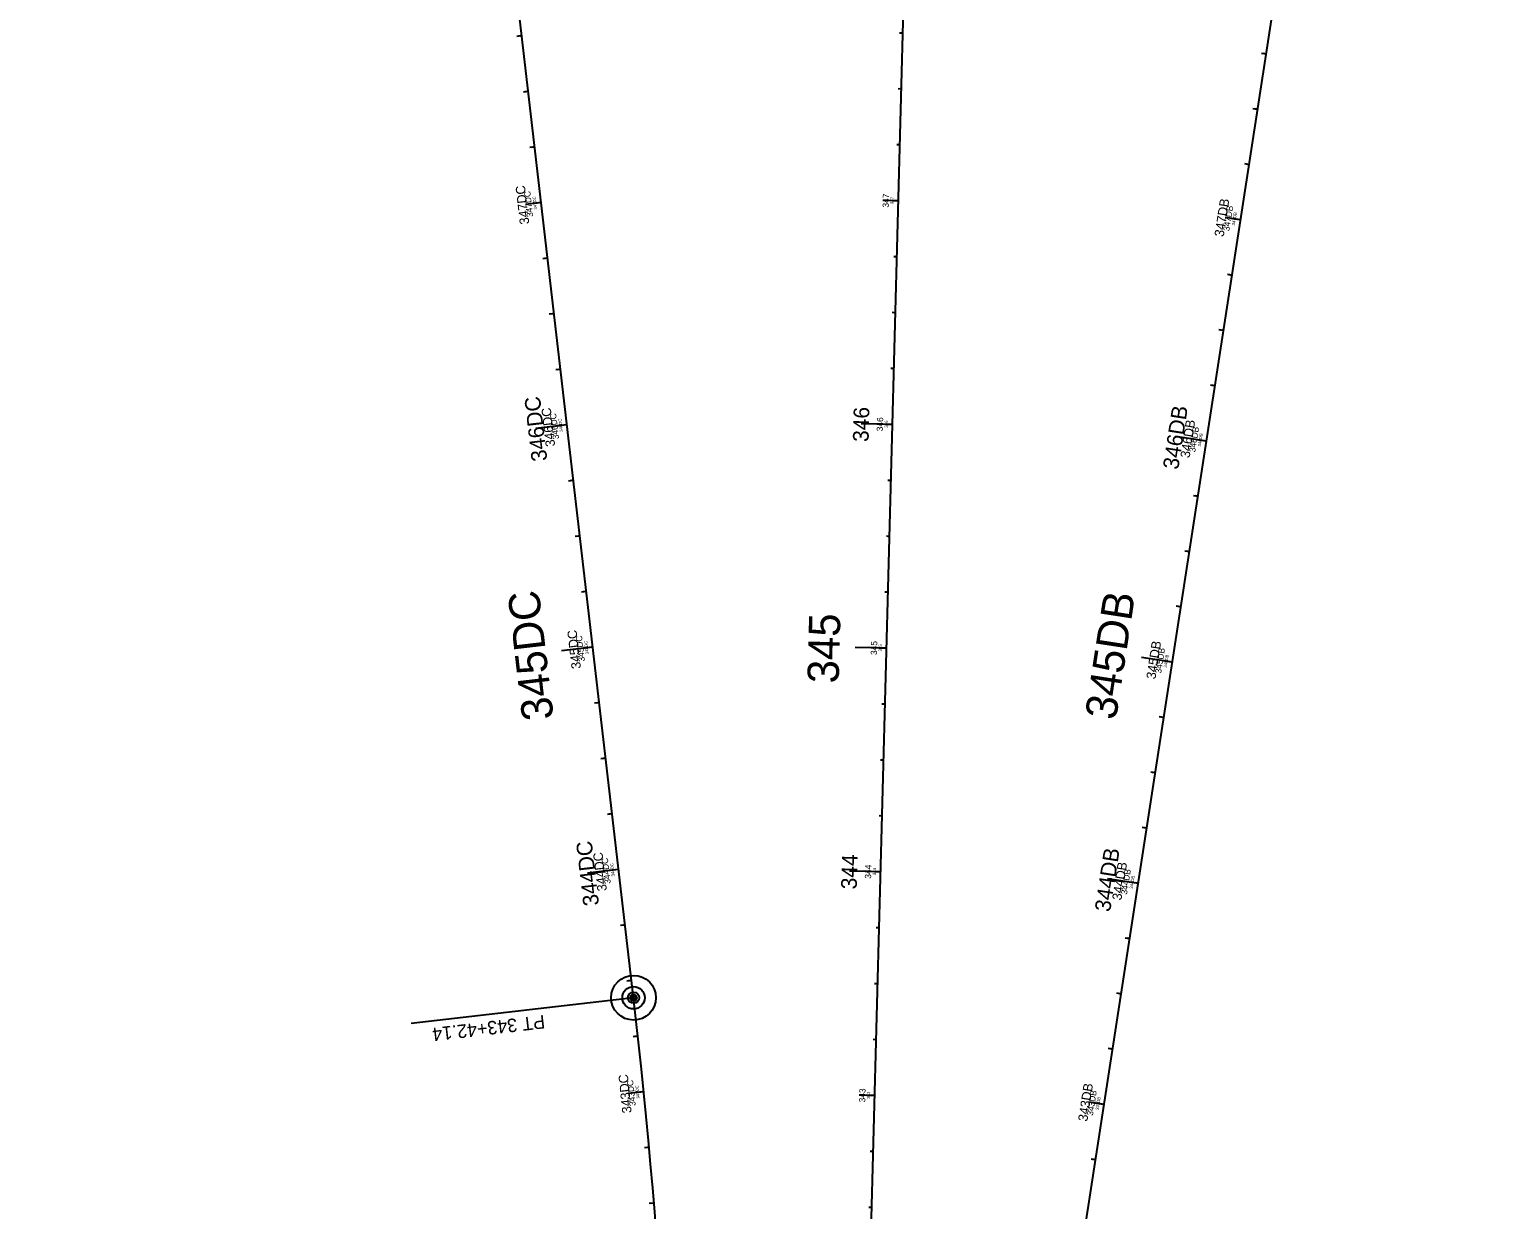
# Model space of a CAD drawing. Extents: x 564646 to 607088, y 225853 to 261760.
# Drawn here: x 598401 to 599063, y 248444 to 248971 of the extents above; entities that cross this region are included whole.
import ezdxf

# ---------------------------------------------------------------- set-up
doc = ezdxf.new("R2010")
doc.units = 0
for name, color, linetype in [('B_CONC_HIDDEN_LT', 7, 'Continuous'), ('B_CONST', 7, 'Continuous'), ('B_EXIST', 7, 'Continuous'), ('B_TEXT', 7, 'Continuous'), ('E-Easements', 7, 'Continuous'), ('E_ALI_100', 7, 'Continuous'), ('E_RW_CorporateLimits', 7, 'Continuous'), ('E_RW_EasementUtility_Text', 7, 'Continuous'), ('E_WTR_FlowLine', 7, 'Continuous'), ('EMCS_SURVEY_PT CODES', 7, 'Continuous'), ('EMCS_SURVEY_PT ELEV', 7, 'Continuous'), ('EMCS_SURVEY_PT NOTES', 7, 'Continuous'), ('Level 33', 7, 'Continuous'), ('P-Easements Floodplain', 7, 'Continuous'), ('P-Easements Temporary', 7, 'Continuous'), ('P_ALI_100_Tic', 7, 'Continuous'), ('P_ALI_20', 7, 'Continuous'), ('P_RW_AccessPreviousProject Txt', 7, 'Continuous'), ('P_RW_EasementPerm', 7, 'Continuous'), ('P_RW_EasementTemp', 7, 'Continuous'), ('P_RW_PropertyConnector', 7, 'Continuous'), ('P_RW_Proposed', 7, 'Continuous'), ('P_WAL', 7, 'Continuous')]:
    doc.layers.add(name, color=color, linetype=linetype)

msp = doc.modelspace()

# ---------------------------------------------------------------- linework, layer by layer
at = {"layer": 'B_CONC_HIDDEN_LT'}
for p, q in [((598400.93, 234167.82), (599016.61, 257518.82)), ((598670.85, 248538.18), (598538.57, 249675.28)), ((598872.31, 248432.59), (599062.75, 249668.45))]:
    msp.add_line(p, q, dxfattribs=at)
msp.add_arc((595889.6, 248214.64), 2800, 359.63542, 6.63542, dxfattribs=at)
at = {"layer": 'B_CONST'}
msp.add_circle((598670.85, 248538.18), 1.5, dxfattribs=at)
at = {"layer": 'B_EXIST'}
msp.add_circle((598670.85, 248538.18), 5, dxfattribs=at)
at = {"layer": 'B_TEXT'}
msp.add_lwpolyline([(598670.85, 248538.18), (598571.51, 248526.63)], dxfattribs=at)
at = {"layer": 'E-Easements'}
msp.add_circle((598670.85, 248538.18), 2.5, dxfattribs=at)
msp.add_circle((598670.85, 248538.18), 2.5, dxfattribs=at)
msp.add_circle((598670.85, 248538.18), 2.5, dxfattribs=at)
at = {"layer": 'E_ALI_100'}
for points in [[(598619.44, 248967.98), (598620.83, 248968.14)], [(598789.79, 248969.45), (598791.19, 248969.41)], [(598952.2, 248960.23), (598953.59, 248960.02)], [(598622.33, 248943.14), (598623.72, 248943.31)], [(598789.13, 248944.46), (598790.53, 248944.42)], [(598948.4, 248935.52), (598949.78, 248935.31)], [(598625.22, 248918.31), (598626.61, 248918.47)], [(598788.48, 248919.47), (598789.88, 248919.43)], [(598944.59, 248910.82), (598945.97, 248910.6)], [(598786.42, 248894.51), (598789.22, 248894.44)], [(598626.71, 248893.32), (598629.49, 248893.64)], [(598939.4, 248886.32), (598942.16, 248885.89)], [(598630.99, 248868.65), (598632.38, 248868.81)], [(598787.16, 248869.48), (598788.56, 248869.45)], [(598936.97, 248861.4), (598938.36, 248861.19)], [(598633.88, 248843.81), (598635.27, 248843.98)], [(598786.5, 248844.49), (598787.9, 248844.46)], [(598933.17, 248836.69), (598934.55, 248836.48)], [(598636.77, 248818.98), (598638.16, 248819.14)], [(598785.84, 248819.5), (598787.24, 248819.46)], [(598929.36, 248811.98), (598930.74, 248811.77)], [(598638.27, 248793.99), (598641.05, 248794.31)], [(598783.78, 248794.55), (598786.58, 248794.47)], [(598924.17, 248787.49), (598926.93, 248787.06)], [(598642.55, 248769.32), (598643.94, 248769.48)], [(598784.52, 248769.52), (598785.92, 248769.48)], [(598921.74, 248762.57), (598923.13, 248762.35)], [(598645.44, 248744.48), (598646.83, 248744.65)], [(598783.86, 248744.53), (598785.26, 248744.49)], [(598917.94, 248737.86), (598919.32, 248737.64)], [(598648.33, 248719.65), (598649.72, 248719.81)], [(598783.2, 248719.54), (598784.6, 248719.5)], [(598914.13, 248713.15), (598915.51, 248712.94)], [(598649.82, 248694.66), (598652.6, 248694.98)], [(598781.15, 248694.58), (598783.94, 248694.51)], [(598908.94, 248688.65), (598911.7, 248688.23)], [(598654.1, 248669.99), (598655.49, 248670.15)], [(598781.89, 248669.55), (598783.29, 248669.52)], [(598906.51, 248663.73), (598907.9, 248663.52)], [(598656.99, 248645.15), (598658.38, 248645.32)], [(598781.23, 248644.56), (598782.63, 248644.52)], [(598902.7, 248639.02), (598904.09, 248638.81)], [(598659.88, 248620.32), (598661.27, 248620.48)], [(598780.57, 248619.57), (598781.97, 248619.53)], [(598898.9, 248614.32), (598900.28, 248614.1)], [(598661.38, 248595.33), (598664.16, 248595.65)], [(598778.51, 248594.62), (598781.31, 248594.54)], [(598893.71, 248589.82), (598896.47, 248589.39)], [(598665.66, 248570.66), (598667.05, 248570.82)], [(598779.25, 248569.59), (598780.65, 248569.55)], [(598891.28, 248564.9), (598892.67, 248564.69)], [(598668.55, 248545.82), (598669.94, 248545.99)], [(598778.59, 248544.6), (598779.99, 248544.56)], [(598887.47, 248540.19), (598888.86, 248539.98)], [(598671.38, 248520.99), (598672.77, 248521.15)], [(598777.93, 248519.61), (598779.33, 248519.57)], [(598883.67, 248515.48), (598885.05, 248515.27)], [(598672.61, 248496), (598675.4, 248496.29)], [(598775.87, 248494.65), (598778.67, 248494.58)], [(598878.48, 248490.99), (598881.24, 248490.56)], [(598676.41, 248471.27), (598677.8, 248471.4)], [(598776.61, 248469.62), (598778.01, 248469.59)], [(598876.05, 248466.07), (598877.44, 248465.85)], [(598678.59, 248446.38), (598679.98, 248446.5)], [(598775.96, 248444.63), (598777.36, 248444.59)]]:
    msp.add_lwpolyline(points, dxfattribs=at)
at = {"layer": 'E_WTR_FlowLine'}
msp.add_circle((598670.85, 248538.18), 0.5, dxfattribs=at)
at = {"layer": 'EMCS_SURVEY_PT CODES'}
for p, q in [((598400.93, 234167.82), (599016.61, 257518.82)), ((598670.85, 248538.18), (598538.57, 249675.28)), ((598670.85, 248538.18), (598538.57, 249675.28)), ((598670.85, 248538.18), (598538.57, 249675.28)), ((598872.31, 248432.59), (599062.75, 249668.45)), ((598872.31, 248432.59), (599062.75, 249668.45)), ((598872.31, 248432.59), (599062.75, 249668.45))]:
    msp.add_line(p, q, dxfattribs=at)
msp.add_arc((595889.6, 248214.64), 2800, 359.63542, 6.63542, dxfattribs=at)
msp.add_arc((595889.6, 248214.64), 2800, 359.63542, 6.63542, dxfattribs=at)
msp.add_arc((595889.6, 248214.64), 2800, 359.63542, 6.63542, dxfattribs=at)
at = {"layer": 'EMCS_SURVEY_PT ELEV'}
for p, q in [((598400.93, 234167.82), (599016.61, 257518.82)), ((598400.93, 234167.82), (599016.61, 257518.82)), ((598670.85, 248538.18), (598538.57, 249675.28)), ((598872.31, 248432.59), (599062.75, 249668.45))]:
    msp.add_line(p, q, dxfattribs=at)
msp.add_arc((595889.6, 248214.64), 2800, 359.63542, 6.63542, dxfattribs=at)
at = {"layer": 'Level 33'}
for points in [[(598620.13, 248968.06), (598620.83, 248968.14)], [(598790.49, 248969.43), (598791.19, 248969.41)], [(598952.89, 248960.13), (598953.59, 248960.02)], [(598623.02, 248943.23), (598623.72, 248943.31)], [(598789.83, 248944.44), (598790.53, 248944.42)], [(598949.09, 248935.42), (598949.78, 248935.31)], [(598625.91, 248918.39), (598626.61, 248918.47)], [(598789.18, 248919.45), (598789.88, 248919.43)], [(598945.28, 248910.71), (598945.97, 248910.6)], [(598787.82, 248894.47), (598789.22, 248894.44)], [(598628.1, 248893.48), (598629.49, 248893.64)], [(598940.78, 248886.11), (598942.16, 248885.89)], [(598631.69, 248868.73), (598632.38, 248868.81)], [(598787.86, 248869.47), (598788.56, 248869.45)], [(598937.66, 248861.29), (598938.36, 248861.19)], [(598634.58, 248843.9), (598635.27, 248843.98)], [(598787.2, 248844.47), (598787.9, 248844.46)], [(598933.86, 248836.58), (598934.55, 248836.48)], [(598637.47, 248819.06), (598638.16, 248819.14)], [(598786.54, 248819.48), (598787.24, 248819.46)], [(598930.05, 248811.88), (598930.74, 248811.77)], [(598639.66, 248794.15), (598641.05, 248794.31)], [(598785.18, 248794.51), (598786.58, 248794.47)], [(598925.55, 248787.27), (598926.93, 248787.06)], [(598643.24, 248769.4), (598643.94, 248769.48)], [(598785.22, 248769.5), (598785.92, 248769.48)], [(598922.43, 248762.46), (598923.13, 248762.35)], [(598646.13, 248744.56), (598646.83, 248744.65)], [(598784.56, 248744.51), (598785.26, 248744.49)], [(598918.63, 248737.75), (598919.32, 248737.64)], [(598649.02, 248719.73), (598649.72, 248719.81)], [(598783.9, 248719.52), (598784.6, 248719.5)], [(598914.82, 248713.04), (598915.51, 248712.94)], [(598651.21, 248694.82), (598652.6, 248694.98)], [(598782.55, 248694.54), (598783.94, 248694.51)], [(598910.32, 248688.44), (598911.7, 248688.23)], [(598654.8, 248670.07), (598655.49, 248670.15)], [(598782.59, 248669.53), (598783.29, 248669.52)], [(598907.2, 248663.63), (598907.9, 248663.52)], [(598657.69, 248645.23), (598658.38, 248645.32)], [(598781.93, 248644.54), (598782.63, 248644.52)], [(598903.4, 248638.92), (598904.09, 248638.81)], [(598660.58, 248620.4), (598661.27, 248620.48)], [(598781.27, 248619.55), (598781.97, 248619.53)], [(598899.59, 248614.21), (598900.28, 248614.1)], [(598662.77, 248595.49), (598664.16, 248595.65)], [(598779.91, 248594.58), (598781.31, 248594.54)], [(598895.09, 248589.61), (598896.47, 248589.39)], [(598666.35, 248570.74), (598667.05, 248570.82)], [(598779.95, 248569.57), (598780.65, 248569.55)], [(598891.97, 248564.79), (598892.67, 248564.69)], [(598669.24, 248545.9), (598669.94, 248545.99)], [(598779.29, 248544.58), (598779.99, 248544.56)], [(598888.17, 248540.08), (598888.86, 248539.98)], [(598672.08, 248521.07), (598672.77, 248521.15)], [(598778.63, 248519.59), (598779.33, 248519.57)], [(598884.36, 248515.38), (598885.05, 248515.27)], [(598674.01, 248496.14), (598675.4, 248496.29)], [(598777.27, 248494.61), (598778.67, 248494.58)], [(598879.86, 248490.77), (598881.24, 248490.56)], [(598677.11, 248471.34), (598677.8, 248471.4)], [(598777.31, 248469.6), (598778.01, 248469.59)], [(598876.74, 248465.96), (598877.44, 248465.85)], [(598679.29, 248446.44), (598679.98, 248446.5)], [(598776.66, 248444.61), (598777.36, 248444.59)]]:
    msp.add_lwpolyline(points, dxfattribs=at)
at = {"layer": 'P-Easements Floodplain'}
for p, q in [((598400.93, 234167.82), (599016.61, 257518.82)), ((598670.85, 248538.18), (598538.57, 249675.28)), ((598872.31, 248432.59), (599062.75, 249668.45))]:
    msp.add_line(p, q, dxfattribs=at)
msp.add_arc((595889.6, 248214.64), 2800, 359.63542, 6.63542, dxfattribs=at)
at = {"layer": 'P-Easements Temporary'}
msp.add_circle((598670.85, 248538.18), 10, dxfattribs=at)
at = {"layer": 'P_ALI_100_Tic'}
for points in [[(598772.59, 248794.84), (598786.58, 248794.47)], [(598627.14, 248792.69), (598641.05, 248794.31)], [(598913.1, 248789.19), (598926.93, 248787.06)], [(598650.25, 248594.03), (598664.16, 248595.65)], [(598767.31, 248594.91), (598781.31, 248594.54)], [(598882.64, 248591.53), (598896.47, 248589.39)]]:
    msp.add_lwpolyline(points, dxfattribs=at)
at = {"layer": 'P_ALI_20'}
for points in [[(598782.22, 248894.62), (598789.22, 248894.44)], [(598622.54, 248892.83), (598629.49, 248893.64)], [(598935.25, 248886.96), (598942.16, 248885.89)], [(598779.58, 248794.66), (598786.58, 248794.47)], [(598634.1, 248793.5), (598641.05, 248794.31)], [(598920.02, 248788.13), (598926.93, 248787.06)], [(598638.7, 248693.36), (598652.6, 248694.98)], [(598769.95, 248694.88), (598783.94, 248694.51)], [(598897.87, 248690.36), (598911.7, 248688.23)], [(598657.21, 248594.84), (598664.16, 248595.65)], [(598774.31, 248594.73), (598781.31, 248594.54)], [(598889.56, 248590.46), (598896.47, 248589.39)], [(598668.44, 248495.58), (598675.4, 248496.29)], [(598771.68, 248494.76), (598778.67, 248494.58)], [(598874.32, 248491.63), (598881.24, 248490.56)]]:
    msp.add_lwpolyline(points, dxfattribs=at)
at = {"layer": 'P_RW_AccessPreviousProject Txt'}
for points in [[(598618.74, 248967.9), (598620.83, 248968.14)], [(598951.51, 248960.34), (598953.59, 248960.02)], [(598621.63, 248943.06), (598623.72, 248943.31)], [(598947.7, 248935.63), (598949.78, 248935.31)], [(598624.52, 248918.23), (598626.61, 248918.47)], [(598943.9, 248910.92), (598945.97, 248910.6)], [(598625.32, 248893.16), (598629.49, 248893.64)], [(598938.01, 248886.53), (598942.16, 248885.89)], [(598630.3, 248868.57), (598632.38, 248868.81)], [(598936.28, 248861.51), (598938.36, 248861.19)], [(598633.19, 248843.73), (598635.27, 248843.98)], [(598932.47, 248836.8), (598934.55, 248836.48)], [(598636.07, 248818.9), (598638.16, 248819.14)], [(598928.67, 248812.09), (598930.74, 248811.77)], [(598636.88, 248793.83), (598641.05, 248794.31)], [(598922.78, 248787.7), (598926.93, 248787.06)], [(598641.85, 248769.24), (598643.94, 248769.48)], [(598921.05, 248762.67), (598923.13, 248762.35)], [(598644.74, 248744.4), (598646.83, 248744.65)], [(598917.24, 248737.96), (598919.32, 248737.64)], [(598647.63, 248719.57), (598649.72, 248719.81)], [(598913.44, 248713.26), (598915.51, 248712.94)], [(598648.43, 248694.5), (598652.6, 248694.98)], [(598907.55, 248688.87), (598911.7, 248688.23)], [(598653.41, 248669.91), (598655.49, 248670.15)], [(598905.82, 248663.84), (598907.9, 248663.52)], [(598656.3, 248645.07), (598658.38, 248645.32)], [(598902.01, 248639.13), (598904.09, 248638.81)], [(598659.19, 248620.24), (598661.27, 248620.48)], [(598898.21, 248614.42), (598900.28, 248614.1)], [(598659.99, 248595.17), (598664.16, 248595.65)], [(598892.32, 248590.03), (598896.47, 248589.39)], [(598664.96, 248570.58), (598667.05, 248570.82)], [(598890.59, 248565.01), (598892.67, 248564.69)], [(598667.85, 248545.74), (598669.94, 248545.99)], [(598886.78, 248540.3), (598888.86, 248539.98)], [(598670.69, 248520.92), (598672.77, 248521.15)], [(598882.98, 248515.59), (598885.05, 248515.27)], [(598671.22, 248495.86), (598675.4, 248496.29)], [(598877.09, 248491.2), (598881.24, 248490.56)], [(598675.71, 248471.21), (598677.8, 248471.4)], [(598875.36, 248466.17), (598877.44, 248465.85)], [(598677.89, 248446.32), (598679.98, 248446.5)]]:
    msp.add_lwpolyline(points, dxfattribs=at)
at = {"layer": 'P_RW_EasementPerm'}
for points in [[(598785.72, 248894.53), (598789.22, 248894.44)], [(598626.02, 248893.24), (598629.49, 248893.64)], [(598938.7, 248886.43), (598942.16, 248885.89)], [(598779.58, 248794.66), (598786.58, 248794.47)], [(598634.1, 248793.5), (598641.05, 248794.31)], [(598920.02, 248788.13), (598926.93, 248787.06)], [(598649.13, 248694.58), (598652.6, 248694.98)], [(598780.45, 248694.6), (598783.94, 248694.51)], [(598908.24, 248688.76), (598911.7, 248688.23)], [(598657.21, 248594.84), (598664.16, 248595.65)], [(598774.31, 248594.73), (598781.31, 248594.54)], [(598889.56, 248590.46), (598896.47, 248589.39)], [(598671.92, 248495.93), (598675.4, 248496.29)], [(598775.17, 248494.67), (598778.67, 248494.58)], [(598877.78, 248491.09), (598881.24, 248490.56)]]:
    msp.add_lwpolyline(points, dxfattribs=at)
at = {"layer": 'P_RW_EasementTemp'}
for p, q in [((598400.93, 234167.82), (599016.61, 257518.82)), ((598670.85, 248538.18), (598538.57, 249675.28)), ((598872.31, 248432.59), (599062.75, 249668.45))]:
    msp.add_line(p, q, dxfattribs=at)
msp.add_arc((595889.6, 248214.64), 2800, 359.63542, 6.63542, dxfattribs=at)
at = {"layer": 'P_RW_PropertyConnector'}
for p, q in [((598400.93, 234167.82), (599016.61, 257518.82)), ((598670.85, 248538.18), (598538.57, 249675.28)), ((598872.31, 248432.59), (599062.75, 249668.45))]:
    msp.add_line(p, q, dxfattribs=at)
msp.add_arc((595889.6, 248214.64), 2800, 359.63542, 6.63542, dxfattribs=at)
at = {"layer": 'P_WAL'}
msp.add_circle((598670.85, 248538.18), 1, dxfattribs=at)

# ---------------------------------------------------------------- texts
for s, rotation, p in [('347DC', 96.63542, (598626.01, 248887.23)), ('347', 88.48966, (598784.93, 248891.24)), ('347DB', 81.23966, (598937.1, 248880.64)), ('346DC', 96.63542, (598637.57, 248787.9)), ('346', 88.48966, (598782.29, 248791.28)), ('346DB', 81.23966, (598921.87, 248781.81)), ('345DC', 96.63542, (598649.12, 248688.57)), ('345', 88.48966, (598779.66, 248691.31)), ('345DB', 81.23966, (598906.64, 248682.97)), ('344DC', 96.63542, (598660.68, 248589.24)), ('344', 88.48966, (598777.02, 248591.35)), ('344DB', 81.23966, (598891.41, 248584.14)), ('343DC', 95.77303, (598671.82, 248489.93)), ('343', 88.48966, (598774.39, 248491.38)), ('343DB', 81.23966, (598876.18, 248485.31))]:
    msp.add_text(s, height=2.8, rotation=rotation).set_placement(p)
at = {"layer": 'B_TEXT'}
msp.add_text('PT 343+42.14', height=6, rotation=186.63542, dxfattribs=at).set_placement((598630.89, 248530.51))
at = {"layer": 'E_RW_CorporateLimits'}
for s, rotation, p in [('345DC', 96.63542, (598635.19, 248662.94)), ('345DB', 81.23966, (598886.41, 248661.96)), ('345', 88.48966, (598762.52, 248678.53))]:
    msp.add_text(s, height=14, rotation=rotation, dxfattribs=at).set_placement(p)
at = {"layer": 'E_RW_EasementUtility_Text'}
for s, rotation, p in [('347DC', 96.63542, (598627.75, 248890.44)), ('347', 88.48966, (598787.07, 248892.84)), ('347DB', 81.23966, (598939.63, 248883.27)), ('346DC', 96.63542, (598639.31, 248791.11)), ('346', 88.48966, (598784.44, 248792.88)), ('346DB', 81.23966, (598924.4, 248784.43)), ('345DC', 96.63542, (598650.86, 248691.78)), ('345', 88.48966, (598781.8, 248692.91)), ('345DB', 81.23966, (598909.17, 248685.6)), ('344DC', 96.63542, (598662.42, 248592.45)), ('344', 88.48966, (598779.17, 248592.94)), ('344DB', 81.23966, (598893.94, 248586.77)), ('343DC', 95.77303, (598673.61, 248493.11)), ('343', 88.48966, (598776.53, 248492.98)), ('343DB', 81.23966, (598878.71, 248487.93))]:
    msp.add_text(s, height=1.4, rotation=rotation, dxfattribs=at).set_placement(p)
at = {"layer": 'EMCS_SURVEY_PT NOTES'}
for s, rotation, p in [('347DC', 96.63542, (598624.27, 248884.03)), ('347DB', 81.23966, (598934.58, 248878.01)), ('346DC', 96.63542, (598635.83, 248784.7)), ('346DB', 81.23966, (598919.34, 248779.18)), ('345DC', 96.63542, (598647.38, 248685.37)), ('345DB', 81.23966, (598904.11, 248680.35)), ('344DC', 96.63542, (598658.94, 248586.04)), ('344DB', 81.23966, (598888.88, 248581.51)), ('343DC', 95.77303, (598670.03, 248486.75)), ('343DB', 81.23966, (598873.65, 248482.68))]:
    msp.add_text(s, height=4.2, rotation=rotation, dxfattribs=at).set_placement(p)
at = {"layer": 'P_RW_Proposed'}
for s, rotation, p in [('346DC', 96.63542, (598632.34, 248778.29)), ('346', 88.48966, (598775.87, 248786.49)), ('346DB', 81.23966, (598914.29, 248773.92)), ('344DC', 96.63542, (598655.45, 248579.63)), ('344DB', 81.23966, (598883.83, 248576.26)), ('344', 88.48966, (598770.59, 248586.55))]:
    msp.add_text(s, height=7, rotation=rotation, dxfattribs=at).set_placement(p)

doc.saveas('drawing.dxf')
